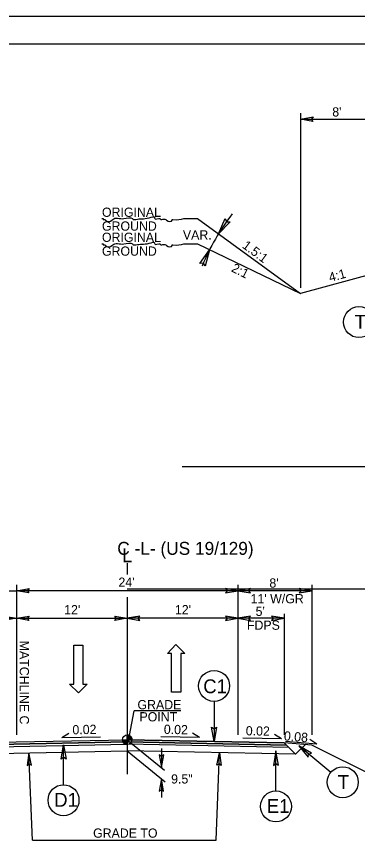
# Model space of a CAD drawing. Extents: x 18938 to 19565, y 6931 to 7973.
# Drawn here: x 19221 to 19258, y 7723.3 to 7812.6 of the extents above; entities that cross this region are included whole.
import ezdxf

# ---------------------------------------------------------------- set-up
doc = ezdxf.new("R2010")
doc.units = 0
for name, color, linetype in [('Old_Level_2', 7, 'Continuous'), ('Prop Dimension', 7, 'Continuous'), ('Prop Pavement Schedule Description CELL', 7, 'Continuous'), ('Prop Shade Light', 7, 'Continuous'), ('Prop Shade Medium', 7, 'Continuous'), ('Prop Terminator CELL', 7, 'Continuous'), ('Sheet Block Title CELL', 7, 'Continuous'), ('Sheet Data Field CELL', 7, 'Continuous'), ('Sheet Plot Border Outside CELL', 7, 'Continuous'), ('Sheet Typical CELL', 7, 'Continuous'), ('Typical Curb CELL', 7, 'Continuous'), ('Typical Detail Wedge1 CELL', 7, 'Continuous'), ('Typical Detail Wedge2 CELL', 7, 'Continuous'), ('Typical Detail Wedge3 CELL', 7, 'Continuous'), ('Typical Guardrail CELL', 7, 'Continuous'), ('Typical Hinge Slope Arterial CELL', 7, 'Continuous'), ('Typical Pavement Slope Information CELL', 7, 'Continuous'), ('Typical Shoulder Slope Information CELL', 7, 'Continuous'), ('Typical Terminator CELL', 7, 'Continuous'), ('Typical Text General CELL', 7, 'Continuous'), ('Typical Text Grade Point CELL', 7, 'Continuous'), ('Typical Text ID Circle CELL', 7, 'Continuous'), ('Typical Text Label CELL', 7, 'Continuous')]:
    doc.layers.add(name, color=color, linetype=linetype)

msp = doc.modelspace()

# ---------------------------------------------------------------- linework, layer by layer
at = {"layer": 'Prop Dimension'}
msp.add_lwpolyline([(19155.167, 7666.179), (19382.434, 7666.179), (19382.434, 7812.613), (19155.167, 7812.613)], close=True, dxfattribs=at)
at = {"layer": 'Prop Pavement Schedule Description CELL'}
for p, q in [((19215.53, 7733.471), (19233.04, 7733.821)), ((19215.785, 7733.726), (19233.04, 7734.071)), ((19216.04, 7733.981), (19233.04, 7734.321)), ((19250.04, 7733.981), (19233.04, 7734.321)), ((19250.295, 7733.726), (19233.04, 7734.071)), ((19250.55, 7733.471), (19233.04, 7733.821)), ((19253.04, 7733.741), (19250.04, 7733.981)), ((19251.287, 7732.735), (19250.04, 7733.981)), ((19251.287, 7732.735), (19252.349, 7733.797)), ((19269.855, 7725.334), (19253.04, 7733.741)), ((19214.793, 7732.735), (19233.04, 7733.1)), ((19251.287, 7732.735), (19233.04, 7733.1))]:
    msp.add_line(p, q, dxfattribs=at)
at = {"layer": 'Prop Shade Medium'}
for p in [(19240.639, 7790.73), (19240.639, 7787.985), (19259.814, 7784.788)]:
    msp.add_line(p, (19251.814, 7782.639), dxfattribs=at)
at = {"layer": 'Sheet Block Title CELL'}
for p, q in [((19215.53, 7733.471), (19233.04, 7733.821)), ((19233.04, 7734.071), (19215.785, 7733.726)), ((19233.04, 7733.821), (19233.04, 7734.071)), ((19233.04, 7734.071), (19250.295, 7733.726)), ((19233.04, 7733.821), (19233.04, 7734.071)), ((19250.55, 7733.471), (19233.04, 7733.821)), ((19250.295, 7733.726), (19250.55, 7733.471))]:
    msp.add_line(p, q, dxfattribs=at)
at = {"layer": 'Sheet Data Field CELL'}
for points in [[(19253.164, 7801.261), (19251.814, 7801.493), (19253.172, 7801.733), (19252.999, 7801.493)], [(19244.187, 7790.396), (19242.925, 7789.075), (19243.67, 7790.756), (19243.807, 7790.386)], [(19240.916, 7785.855), (19241.96, 7787.353), (19241.482, 7785.578), (19241.29, 7785.922)], [(19222.39, 7750.214), (19221.04, 7750.447), (19222.398, 7750.687), (19222.225, 7750.447)], [(19243.69, 7750.214), (19245.04, 7750.447), (19243.683, 7750.687), (19243.855, 7750.447)], [(19246.39, 7750.679), (19245.04, 7750.447), (19246.398, 7750.207), (19246.225, 7750.447)], [(19251.69, 7750.214), (19253.04, 7750.447), (19251.683, 7750.687), (19251.855, 7750.447)], [(19219.69, 7747.702), (19221.04, 7747.469), (19219.683, 7747.229), (19219.855, 7747.469)], [(19222.39, 7747.237), (19221.04, 7747.469), (19222.398, 7747.709), (19222.225, 7747.469)], [(19231.69, 7747.702), (19233.04, 7747.469), (19231.683, 7747.229), (19231.855, 7747.469)], [(19234.39, 7747.702), (19233.04, 7747.469), (19234.398, 7747.229), (19234.225, 7747.469)], [(19243.69, 7747.237), (19245.04, 7747.469), (19243.683, 7747.709), (19243.855, 7747.469)], [(19246.39, 7747.702), (19245.04, 7747.469), (19246.398, 7747.229), (19246.225, 7747.469)], [(19248.69, 7747.237), (19250.04, 7747.469), (19248.683, 7747.709), (19248.855, 7747.469)], [(19222.67, 7731.545), (19222.392, 7732.887), (19222.198, 7731.522), (19222.432, 7731.702)], [(19242.759, 7731.558), (19243.036, 7732.9), (19243.231, 7731.535), (19242.997, 7731.715)], [(19236.517, 7732.667), (19236.75, 7731.317), (19236.99, 7732.674), (19236.75, 7732.502)], [(19236.982, 7728.743), (19236.749, 7730.093), (19236.509, 7728.736), (19236.749, 7728.908)]]:
    msp.add_lwpolyline(points, close=True, dxfattribs=at)
at = {"layer": 'Sheet Typical CELL'}
for p, q in [((19251.814, 7802.149), (19251.814, 7783.228)), ((19251.814, 7801.493), (19259.814, 7801.493)), ((19221.04, 7751.103), (19221.04, 7734.841)), ((19245.04, 7751.103), (19245.04, 7734.841)), ((19253.04, 7751.103), (19253.04, 7734.841)), ((19213.04, 7750.447), (19221.04, 7750.447)), ((19245.04, 7750.447), (19221.04, 7750.447)), ((19253.04, 7750.447), (19245.04, 7750.447)), ((19216.04, 7747.469), (19221.04, 7747.469)), ((19221.04, 7747.469), (19233.04, 7747.469)), ((19245.04, 7747.469), (19233.04, 7747.469)), ((19250.04, 7747.469), (19245.04, 7747.469)), ((19250.04, 7747.93), (19250.04, 7734.841)), ((19233.04, 7734.321), (19237.096, 7731.037)), ((19222.761, 7723.43), (19222.392, 7732.887)), ((19233.04, 7733.098), (19237.145, 7729.773)), ((19236.75, 7733.361), (19236.75, 7731.317)), ((19242.667, 7723.43), (19243.036, 7732.9)), ((19236.749, 7730.093), (19236.749, 7728.07)), ((19222.761, 7723.43), (19242.667, 7723.43))]:
    msp.add_line(p, q, dxfattribs=at)
msp.add_arc((19264.24, 7776.012), 25, 142.49775, 157.45327, dxfattribs=at)
at = {"layer": 'Typical Curb CELL'}
for points in [[(19230.275, 7790.73), (19230.446, 7790.73), (19230.446, 7790.645), (19230.618, 7790.645), (19230.703, 7790.559), (19231.389, 7790.559), (19231.474, 7790.645), (19232.673, 7790.73), (19233.615, 7790.73), (19233.701, 7790.645), (19233.958, 7790.645), (19235.414, 7790.816), (19236.014, 7790.816), (19236.014, 7790.73), (19236.613, 7790.73), (19236.699, 7790.645), (19236.785, 7790.645), (19237.213, 7790.645), (19237.299, 7790.559), (19237.898, 7790.559), (19237.898, 7790.645), (19237.984, 7790.645), (19239.183, 7790.73), (19240.553, 7790.73), (19240.639, 7790.73)], [(19230.275, 7787.985), (19230.446, 7787.985), (19230.446, 7787.899), (19230.618, 7787.899), (19230.703, 7787.813), (19231.389, 7787.813), (19231.474, 7787.899), (19232.673, 7787.985), (19233.615, 7787.985), (19233.701, 7787.899), (19233.958, 7787.899), (19235.414, 7788.07), (19236.014, 7788.07), (19236.014, 7787.985), (19236.613, 7787.985), (19236.699, 7787.899), (19236.785, 7787.899), (19237.213, 7787.899), (19237.299, 7787.813), (19237.898, 7787.813), (19237.898, 7787.899), (19237.984, 7787.899), (19239.183, 7787.985), (19240.553, 7787.985), (19240.639, 7787.985)]]:
    msp.add_spline(points, degree=3, dxfattribs=at)
at = {"layer": 'Typical Detail Wedge1 CELL'}
for p, q in [((19233.04, 7734.321), (19233.04, 7734.833)), ((19232.528, 7734.321), (19233.04, 7734.321)), ((19233.552, 7734.321), (19233.04, 7734.321)), ((19233.04, 7733.809), (19233.04, 7734.321)), ((19233.04, 7734.321), (19233.04, 7733.809))]:
    msp.add_line(p, q, dxfattribs=at)
for points in [[(19233.045, 7734.833), (19233.045, 7734.833), (19233.045, 7734.321)], [(19233.056, 7734.833), (19233.055, 7734.321)], [(19233.066, 7734.833), (19233.066, 7734.321)], [(19233.076, 7734.832), (19233.076, 7734.321)], [(19233.086, 7734.831), (19233.086, 7734.321)], [(19233.096, 7734.83), (19233.096, 7734.321)], [(19233.107, 7734.829), (19233.107, 7734.321)], [(19233.117, 7734.828), (19233.117, 7734.321)], [(19233.127, 7734.826), (19233.127, 7734.321)], [(19233.137, 7734.824), (19233.137, 7734.321)], [(19233.148, 7734.822), (19233.147, 7734.321)], [(19233.158, 7734.82), (19233.158, 7734.321)], [(19233.168, 7734.817), (19233.168, 7734.321)], [(19233.178, 7734.814), (19233.178, 7734.321)], [(19233.188, 7734.811), (19233.188, 7734.321)], [(19233.199, 7734.808), (19233.199, 7734.321)], [(19233.209, 7734.805), (19233.209, 7734.321)], [(19233.219, 7734.801), (19233.219, 7734.321)], [(19233.23, 7734.797), (19233.23, 7734.321)], [(19233.24, 7734.793), (19233.24, 7734.321)], [(19233.25, 7734.788), (19233.25, 7734.321)], [(19233.26, 7734.784), (19233.26, 7734.321)], [(19233.271, 7734.779), (19233.271, 7734.321)], [(19233.281, 7734.773), (19233.281, 7734.321)], [(19233.291, 7734.768), (19233.291, 7734.321)], [(19233.301, 7734.762), (19233.301, 7734.321)], [(19233.312, 7734.756), (19233.311, 7734.321)], [(19233.322, 7734.749), (19233.322, 7734.321)], [(19233.332, 7734.742), (19233.332, 7734.321)], [(19233.342, 7734.735), (19233.342, 7734.321)], [(19233.352, 7734.727), (19233.352, 7734.321)], [(19233.363, 7734.719), (19233.362, 7734.321)], [(19233.373, 7734.711), (19233.373, 7734.321)], [(19233.383, 7734.701), (19233.383, 7734.321)], [(19233.393, 7734.692), (19233.393, 7734.321)], [(19233.403, 7734.682), (19233.403, 7734.321)], [(19233.414, 7734.671), (19233.414, 7734.321)], [(19233.424, 7734.66), (19233.424, 7734.321)], [(19233.434, 7734.648), (19233.434, 7734.321)], [(19233.445, 7734.635), (19233.445, 7734.321)], [(19232.531, 7734.321), (19232.531, 7734.265)], [(19232.541, 7734.321), (19232.541, 7734.205)], [(19232.552, 7734.321), (19232.552, 7734.168)], [(19232.562, 7734.321), (19232.562, 7734.139)], [(19232.572, 7734.321), (19232.572, 7734.114)], [(19232.582, 7734.321), (19232.582, 7734.092)], [(19232.593, 7734.321), (19232.593, 7734.072)], [(19232.603, 7734.321), (19232.603, 7734.055)], [(19232.613, 7734.321), (19232.613, 7734.039)], [(19232.623, 7734.321), (19232.623, 7734.024)], [(19232.634, 7734.321), (19232.634, 7734.011)], [(19232.644, 7734.321), (19232.644, 7733.997)], [(19232.654, 7734.321), (19232.654, 7733.985)], [(19232.664, 7734.321), (19232.664, 7733.974)], [(19232.674, 7734.321), (19232.674, 7733.963)], [(19232.685, 7734.321), (19232.684, 7733.953)], [(19232.695, 7734.321), (19232.695, 7733.943)], [(19232.705, 7734.321), (19232.705, 7733.934)], [(19232.715, 7734.321), (19232.715, 7733.925)], [(19232.726, 7734.321), (19232.726, 7733.917)], [(19232.736, 7734.321), (19232.736, 7733.91)], [(19232.746, 7734.321), (19232.746, 7733.902)], [(19232.757, 7734.321), (19232.756, 7733.895)], [(19232.767, 7734.321), (19232.767, 7733.888)], [(19232.777, 7734.321), (19232.777, 7733.882)], [(19232.787, 7734.321), (19232.787, 7733.876)], [(19232.797, 7734.321), (19232.797, 7733.871)], [(19232.808, 7734.321), (19232.808, 7733.865)], [(19232.818, 7734.321), (19232.818, 7733.86)], [(19232.828, 7734.321), (19232.828, 7733.856)], [(19232.838, 7734.321), (19232.838, 7733.851)], [(19232.849, 7734.321), (19232.848, 7733.847)], [(19232.859, 7734.321), (19232.859, 7733.843)], [(19232.869, 7734.321), (19232.869, 7733.839)], [(19232.879, 7734.321), (19232.879, 7733.835)], [(19232.889, 7734.321), (19232.889, 7733.832)], [(19232.9, 7734.321), (19232.899, 7733.829)], [(19232.91, 7734.321), (19232.91, 7733.826)], [(19232.92, 7734.321), (19232.92, 7733.824)], [(19232.93, 7734.321), (19232.93, 7733.821)], [(19232.941, 7734.321), (19232.941, 7733.819)], [(19232.951, 7734.321), (19232.951, 7733.817)], [(19232.961, 7734.321), (19232.961, 7733.816)], [(19232.972, 7734.321), (19232.972, 7733.814)], [(19232.982, 7734.321), (19232.982, 7733.813)], [(19232.992, 7734.321), (19232.992, 7733.812)], [(19233.002, 7734.321), (19233.002, 7733.811)], [(19233.013, 7734.321), (19233.012, 7733.81)], [(19233.023, 7734.321), (19233.023, 7733.81)], [(19233.033, 7734.321), (19233.033, 7733.809), (19233.033, 7733.809)], [(19233.455, 7734.622), (19233.455, 7734.321)], [(19233.465, 7734.607), (19233.465, 7734.321)], [(19233.475, 7734.591), (19233.475, 7734.321)], [(19233.486, 7734.574), (19233.486, 7734.321)], [(19233.496, 7734.555), (19233.496, 7734.321)], [(19233.506, 7734.534), (19233.506, 7734.321)], [(19233.516, 7734.51), (19233.516, 7734.321)], [(19233.526, 7734.481), (19233.526, 7734.321)], [(19233.537, 7734.446), (19233.537, 7734.321)], [(19233.547, 7734.394), (19233.547, 7734.321)]]:
    msp.add_lwpolyline(points, dxfattribs=at)
msp.add_circle((19233.04, 7734.321), 0.512, dxfattribs=at)
for start, end in [(359.99048, 89.99048), (179.99048, 269.99048)]:
    msp.add_arc((19233.04, 7734.321), 0.512, start, end, dxfattribs=at)
at = {"layer": 'Typical Detail Wedge3 CELL'}
for p, q in [((19227.247, 7740.34), (19227.247, 7744.54)), ((19227.247, 7744.54), (19228.237, 7744.54)), ((19228.237, 7744.54), (19228.237, 7740.34)), ((19237.393, 7743.669), (19238.323, 7744.614)), ((19238.323, 7744.614), (19239.283, 7743.669)), ((19237.843, 7743.669), (19237.393, 7743.669)), ((19237.843, 7739.469), (19237.843, 7743.669)), ((19239.283, 7743.669), (19238.833, 7743.669)), ((19238.833, 7743.669), (19238.833, 7739.469)), ((19227.757, 7739.395), (19226.797, 7740.34)), ((19226.797, 7740.34), (19227.247, 7740.34)), ((19228.687, 7740.34), (19227.757, 7739.395)), ((19228.237, 7740.34), (19228.687, 7740.34)), ((19238.833, 7739.469), (19237.843, 7739.469))]:
    msp.add_line(p, q, dxfattribs=at)
at = {"layer": 'Typical Guardrail CELL'}
for p, q in [((19239.008, 7763.885), (19386.11, 7763.885)), ((19233.04, 7750.645), (19380.142, 7750.645))]:
    msp.add_line(p, q, dxfattribs=at)
at = {"layer": 'Typical Hinge Slope Arterial CELL'}
for p, q in [((19216.04, 7733.981), (19233.04, 7734.321)), ((19233.04, 7734.071), (19219.785, 7733.806)), ((19233.04, 7734.321), (19250.04, 7733.981)), ((19250.295, 7733.726), (19233.04, 7734.071)), ((19250.04, 7733.981), (19250.295, 7733.726))]:
    msp.add_line(p, q, dxfattribs=at)
at = {"layer": 'Typical Pavement Slope Information CELL'}
msp.add_lwpolyline([(19380.142, 7809.605), (19177.642, 7809.605), (19177.642, 7669.19), (19380.142, 7669.19)], close=True, dxfattribs=at)
at = {"layer": 'Typical Terminator CELL'}
for p, q in [((19242.455, 7738.464), (19242.455, 7734.133)), ((19226.137, 7729.442), (19226.137, 7733.773)), ((19249.158, 7728.773), (19249.158, 7733.104)), ((19255.102, 7730.782), (19251.624, 7733.641))]:
    msp.add_line(p, q, dxfattribs=at)
for centre in [(19258.156, 7779.528), (19242.455, 7740.14), (19256.397, 7729.718), (19226.137, 7727.766), (19249.158, 7727.097)]:
    msp.add_circle(centre, 1.676, dxfattribs=at)
at = {"layer": 'Typical Text General CELL'}
for points in [[(19242.723, 7735.685), (19242.455, 7734.133), (19242.18, 7735.694), (19242.455, 7735.495)], [(19225.87, 7732.221), (19226.137, 7733.773), (19226.413, 7732.213), (19226.137, 7732.411)], [(19249.425, 7731.552), (19249.158, 7733.104), (19248.882, 7731.544), (19249.158, 7731.742)], [(19252.993, 7732.862), (19251.624, 7733.641), (19252.654, 7732.437), (19252.676, 7732.776)]]:
    msp.add_lwpolyline(points, close=True, dxfattribs=at)
at = {"layer": 'Typical Text Grade Point CELL'}
for p, q in [((19225.944, 7734.562), (19226.727, 7735.035)), ((19225.944, 7734.562), (19230.133, 7734.645)), ((19240.888, 7734.562), (19236.7, 7734.645)), ((19240.888, 7734.562), (19240.105, 7735.035)), ((19249.767, 7734.405), (19248.984, 7734.878)), ((19249.767, 7734.405), (19245.578, 7734.489)), ((19253.593, 7733.838), (19250.207, 7734.109)), ((19253.593, 7733.838), (19252.84, 7734.357))]:
    msp.add_line(p, q, dxfattribs=at)
at = {"layer": 'Typical Text ID Circle CELL'}
for p, q in [((19233.04, 7753.445), (19233.04, 7752.197)), ((19233.04, 7749.765), (19233.04, 7730.585)), ((19233.29, 7734.774), (19233.785, 7737.442)), ((19238.863, 7737.442), (19233.785, 7737.442))]:
    msp.add_line(p, q, dxfattribs=at)

# ---------------------------------------------------------------- texts
at = {"layer": 'Old_Level_2'}
for s, p in [('ORIGINAL', (19230.302, 7790.923)), ('GROUND', (19230.302, 7789.423)), ('ORIGINAL', (19230.302, 7788.214)), ('GROUND', (19230.302, 7786.714))]:
    msp.add_text(s, height=1, rotation=360, dxfattribs=at).set_placement(p)
at = {"layer": 'Prop Shade Light'}
msp.add_text('VAR.', height=1, rotation=360, dxfattribs=at).set_placement((19239.073, 7788.469))
at = {"layer": 'Prop Terminator CELL'}
for s, p in [('T', (19257.687, 7778.808)), ('E1', (19248.166, 7726.386))]:
    msp.add_text(s, height=1.5, rotation=360, dxfattribs=at).set_placement(p)
for s, p in [('C1', (19241.282, 7739.352)), ('T', (19255.852, 7728.998)), ('D1', (19225.126, 7727.055))]:
    msp.add_text(s, height=1.5, dxfattribs=at).set_placement(p)
at = {"layer": 'Sheet Plot Border Outside CELL'}
for s, p in [('GRADE', (19234.151, 7737.611)), ('POINT', (19234.369, 7736.3))]:
    msp.add_text(s, height=1, rotation=0.00004, dxfattribs=at).set_placement(p)
at = {"layer": 'Typical Detail Wedge2 CELL'}
for s, p in [("8'", (19255.26, 7801.783)), ("24'", (19232.091, 7750.873)), ("8'", (19248.445, 7750.784)), ("11' W/GR", (19246.413, 7749.084)), ("12'", (19226.21, 7747.895)), ("12'", (19238.21, 7747.895)), ("5'", (19246.953, 7747.719)), ('FDPS', (19246.013, 7746.219)), ('9.5"', (19237.798, 7729.573)), ('GRADE TO', (19229.341, 7723.707))]:
    msp.add_text(s, height=1, dxfattribs=at).set_placement(p)
msp.add_text('MATCHLINE C', height=1, rotation=270, dxfattribs=at).set_placement((19221.395, 7745.036))
at = {"layer": 'Typical Shoulder Slope Information CELL'}
for s, rotation, p in [('1.5:1', 323.55802, (19245.428, 7787.641)), ('2:1', 333.43491, (19244.241, 7785.055)), ('4:1', 15.1346, (19255.03, 7783.864))]:
    msp.add_text(s, height=1, rotation=rotation, dxfattribs=at).set_placement(p)
at = {"layer": 'Typical Text Grade Point CELL'}
for s, rotation, p in [('0.02', 1.14574, (19227.112, 7734.896)), ('0.02', 358.85426, (19237.003, 7734.951)), ('0.02', 358.85426, (19245.882, 7734.794)), ('0.08', 355.4262, (19249.989, 7734.252))]:
    msp.add_text(s, height=1, rotation=rotation, dxfattribs=at).set_placement(p)
at = {"layer": 'Typical Text Label CELL'}
for s, height, p in [('C -L- (US 19/129)', 1.4, (19231.962, 7754.334)), ('L', 1.5, (19232.478, 7753.528))]:
    msp.add_text(s, height=height, dxfattribs=at).set_placement(p)

doc.saveas('drawing.dxf')
